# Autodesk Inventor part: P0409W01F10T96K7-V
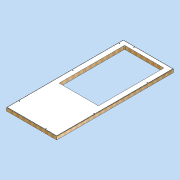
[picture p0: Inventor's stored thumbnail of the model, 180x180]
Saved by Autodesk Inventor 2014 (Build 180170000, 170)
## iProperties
Created: 2011-04
Part Number: P0409W01F10T96K7-V
Document SubType Name: Modeling
Designer: david.appleford
Density: 0.181403 g/cm^3
Description: 1w x 2.25w  01 Panel - 7 Locks
Cost Center: £143.00
Mass: 25000 g
Surface Area: 44638.2 cm^2
Volume: 137814 cm^3
Material: Generic
Appearance: Wood (Pine)
Justset: False
Title: 1w x 2.25w  01 Panel - 7 Locks
Author: david.appleford
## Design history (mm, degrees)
sketch "Sketch1"
  geometry: L1 (0, 0)-(1220, 0); L2 (1220, 0)-(1220, 2745); L3 (1220, 2745)-(0, 2745); L4 (0, 2745)-(0, 0); L5 (34, 2711)-(1186, 2711); L6 (1186, 2711)-(1186, 34); L7 (1186, 34)-(34, 34); L8 (34, 34)-(34, 2711)
  constraints: 16 end point, 4 parallel, 2 perpendicular, 1 horizontal, 3 other
  dimensions: "d0" = 1220 distance between parallel lines of L2 L4 (= w); "d1" = 2745 distance between parallel lines of L1 L3 (= 2.25 x w); "d2" = 34 distance between parallel lines of L5 L3 (= 0.5 x t); "d29" = 2677 distance between parallel lines of L7 L5 (derived); "d30" = 1152 distance between parallel lines of L6 L8 (derived)
extrude "Extrusion1" new body sketch "Sketch1" distance "d3" = 68 (= t); taper "d4" = 0 deg
sketch "Sketch2"
  geometry: L1 (1186, 2711)-(1186, 34) reference; L2 (34, 2711)-(1186, 2711) reference; L3 (34, 34)-(34, 2711) reference; L4 (1186, 34)-(34, 34) reference; L5 (1176, 2701)-(1176, 44); L6 (1176, 44)-(44, 44); L7 (44, 44)-(44, 2701); L8 (44, 2701)-(1176, 2701); 1 further point
  constraints: 8 end point, 3 other
  dimensions: "d5" = 10 distance between parallel lines of L8 L2
extrude "Extrusion2" join sketch "Sketch2" distance "d6" = 6 (= sw); taper "d7" = 0 deg
sketch "Sketch3"
  geometry: L1 (-44, 2701)-(-1176, 2701) reference; L2 (-1176, 2701)-(-1176, 44) reference; L3 (-44, 44)-(-44, 2701) reference; L4 (-1176, 44)-(-44, 44) reference; 1 further point
extrude "Extrusion3" join sketch "Sketch3" distance "d8" = 6 (= sw); taper "d9" = 0 deg
sketch "Sketch4"
  geometry: L1 (34, 2711)-(1186, 2711) reference; L2 (1186, 2711)-(1186, 34) reference; L3 (1186, 34)-(34, 34) reference; L4 (34, 34)-(34, 2711) reference; 8 further points
  constraints: 3 vertical alignment
  dimensions: "d10" = 28 distance from line of point (305, 2683) L1 (= k); "d12" = 28 distance from line of L3 point (915, 62) (= k); "d13" = 28 distance from line of point (62, 305) L4 (= k); "d14" = 305 horizontal distance of point (305, 2683) point (0, 0) (= 0.25 x w); "d15" = 610 horizontal distance of point (915, 62) point (305, 2683) (= 0.5 x w); "d16" = 305 vertical distance of point (62, 305) point (0, 0) (= 0.25 x w); "d17" = 1220 distance of point (62, 305) point (62, 1525) (= w); "d19" = 610 vertical distance of point (1158, 915) point (62, 305) (= 0.5 x w); "d20" = 1220 distance of point (1158, 915) point (1158, 2135) (= w); "d31" = 1067.5 distance of point (62, 1525) point (62, 2592.5)
hole "Hole1" sketch "Sketch4" at (305, 2683), (62, 1525), (62, 305), (1158, 2135), (1158, 915), (915, 62), (62, 2592.5) diameter "d22" = 16.3; stored, may be unused: countersink angle "d26" = 90 deg, drill point angle "d28" = 118 deg; dims "d23" = 6, "d24" = 4, "d25" = 2, "d27" = 6
sketch "Sketch5"
  geometry: L1 (180, 2615)-(1040, 2615); L2 (1060, 2595)-(1060, 1135); L3 (1040, 1115)-(180, 1115); L4 (160, 1135)-(160, 2595); L5 (34, 2711)-(1186, 2711) reference; L6 (34, 34)-(34, 2711) reference; L7 (1186, 2711)-(1186, 34) reference; A1 r 20 centre (180, 2595) between (180, 2615) and (160, 2595); A2 r 20 centre (1040, 2595) between (1060, 2595) and (1040, 2615); A3 r 20 centre (1040, 1135) between (1040, 1115) and (1060, 1135); A4 r 20 centre (180, 1135) between (160, 1135) and (180, 1115); 1 further point
  constraints: 8 end point, 8 point on circle, 8 tangent, 4 centre point, 3 equal radius
  dimensions: "d32" = 96 distance between parallel lines of L5 L1; "d33" = 1500 distance between parallel lines of L3 L1; "d34" = 126 distance between parallel lines of L6 L4 (= -0.5 x d36 + 0.5 x d35); "d35" = 1152 distance between parallel lines of L7 L6 (derived); "d36" = 900 distance between parallel lines of L2 L4; "d37" = 20 radius of A1
extrude "Extrusion4" cut sketch "Sketch5" stored distance "d38" = 10; taper "d39" = 0 deg
body "Solid1"
node "Projected Loop1"
other parameters: "w" = 1220 [user parameter; used in 8 equation terms], "t" = 68 [user parameter; used in 2 equation terms], "e" = 16 [user parameter], "sw" = 6 [user parameter; used in 2 equation terms], "sc" = 9 [user parameter], "sf" = 12 [user parameter], "k" = 28 [user parameter; used in 3 equation terms], "hd" = 12 [user parameter]
